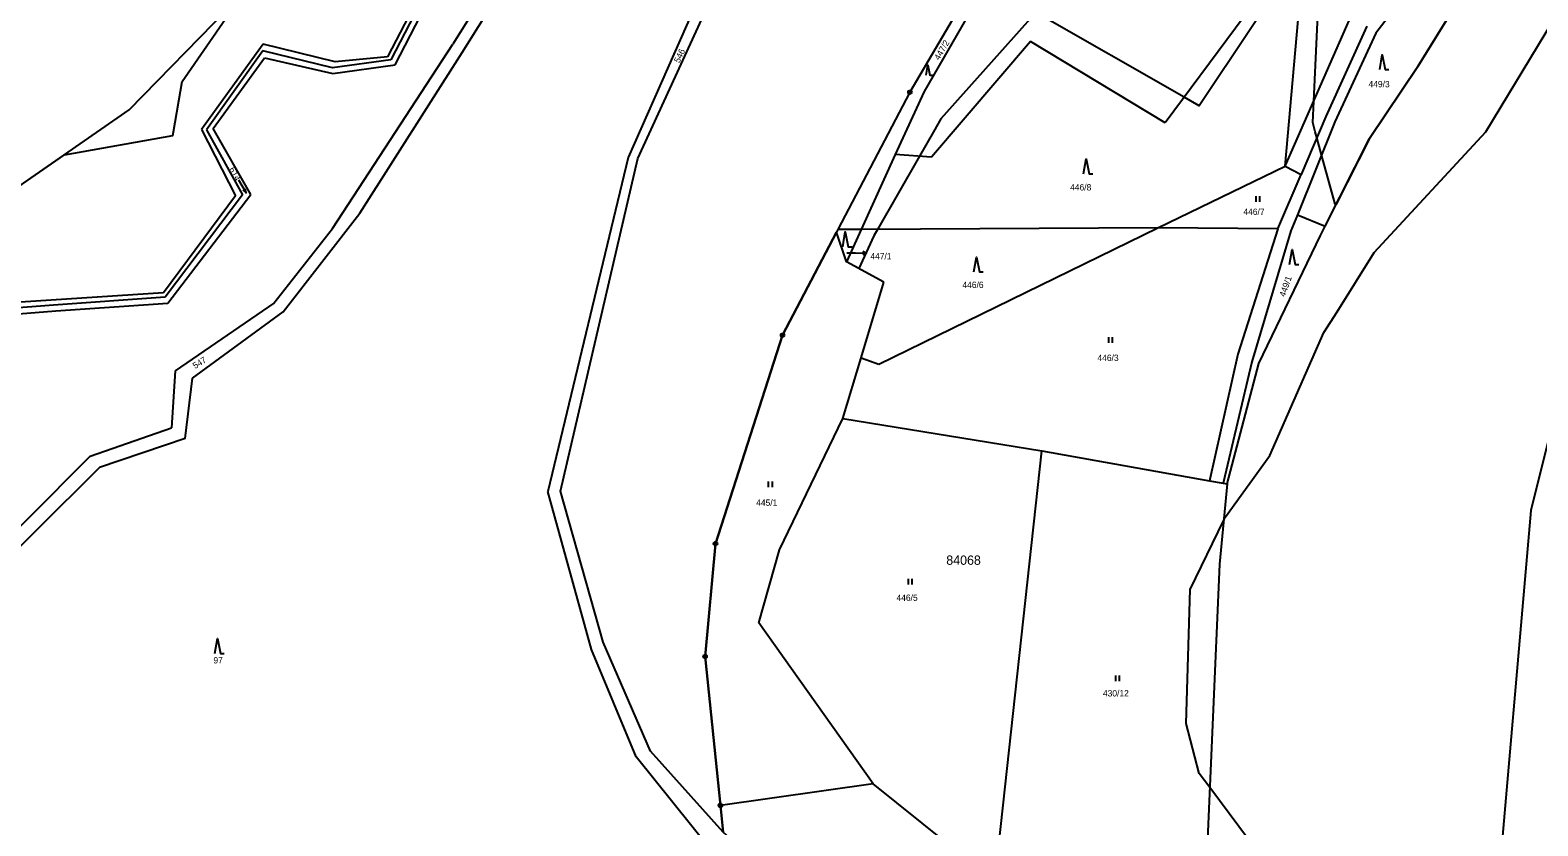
# Model space of a CAD drawing. Extents: x -547623 to -538651, y -1096714 to -1086522.
# Drawn here: x -544381.9 to -543976.5, y -1094186.5 to -1093972.7 of the extents above; entities that cross this region are included whole.
import ezdxf

# ---------------------------------------------------------------- set-up
doc = ezdxf.new("R2010")
doc.units = 0
for name, color, linetype in [('podzemní_provozovana', 7, 'Continuous'), ('Vrstva 1', 7, 'Continuous'), ('Vrstva 25', 7, 'Continuous'), ('Vrstva 41', 7, 'Continuous'), ('Vrstva 52', 7, 'Continuous'), ('Vrstva 53', 7, 'Continuous'), ('Vrstva 83', 7, 'Continuous'), ('Vrstva 86', 7, 'Continuous')]:
    doc.layers.add(name, color=color, linetype=linetype)

msp = doc.modelspace()

# ---------------------------------------------------------------- linework, layer by layer
at = {"layer": 'podzemní_provozovana'}
msp.add_line((-544159.95, -1094032.56), (-544156.95, -1094032.62), dxfattribs=at)
for points in [[(-544157.94, -1094032.1), (-544156.95, -1094032.62), (-544157.96, -1094033.1)], [(-544162.29, -1094032.52), (-544159.95, -1094032.56)]]:
    msp.add_lwpolyline(points, dxfattribs=at)
at = {"layer": 'Vrstva 1'}
for points in [[(-544231.42, -1093917.78), (-544268.23, -1093976.49)], [(-544265.71, -1093978.73), (-544229.5, -1093920.98)], [(-544102, -1093920.7), (-544141.53, -1093989.17)], [(-544038.86, -1093946.61), (-544076.64, -1093997.58)], [(-544044.44, -1094009.29), (-544038.86, -1093946.61)], [(-544196.54, -1093951.3), (-544221.1, -1094006.97)], [(-544218.52, -1094007.2), (-544194.16, -1093954.3)], [(-544009.71, -1093960.09), (-544020, -1093973.55)], [(-544355.24, -1093994.15), (-544328.67, -1093966.87)], [(-544008.7, -1093982.5), (-543998.69, -1093966.28)], [(-544280.03, -1093968.88), (-544285.81, -1093979.92)], [(-544283.7, -1093982.03), (-544276.92, -1093968.88)], [(-544044.44, -1094009.29), (-544026.22, -1093967.89)], [(-544022.47, -1093971.59), (-544033.52, -1093995.88)], [(-544020, -1093973.55), (-544031.03, -1093997.36)], [(-544319.25, -1093976.47), (-544335.83, -1093999.42)], [(-544299.85, -1093981.24), (-544319.25, -1093976.47)], [(-544300.62, -1094025.98), (-544268.23, -1093976.49)], [(-544293.25, -1094021.87), (-544265.71, -1093978.73)], [(-544112.85, -1093975.79), (-544139.51, -1094006.81)], [(-544076.64, -1093997.58), (-544112.85, -1093975.79)], [(-544332.64, -1093999.18), (-544318.88, -1093980.1)], [(-544318.88, -1093980.1), (-544300.51, -1093984.31)], [(-544300.51, -1093984.31), (-544283.7, -1093982.03)], [(-544285.81, -1093979.92), (-544299.85, -1093981.24)], [(-544021.73, -1094001.81), (-544008.7, -1093982.5)], [(-544141.53, -1093989.17), (-544149.24, -1094006.09)], [(-544410.07, -1094032.13), (-544355.24, -1093994.15)], [(-544335.83, -1093999.42), (-544326.66, -1094017.24)], [(-544322.54, -1094016.84), (-544332.64, -1093999.18)], [(-544031.03, -1093997.36), (-544041.14, -1094022.36)], [(-544033.52, -1093995.88), (-544040.1, -1094011.54)], [(-544033.7, -1094025.42), (-544021.73, -1094001.81)], [(-544221.1, -1094006.97), (-544242.67, -1094096.71)], [(-544239.27, -1094096.59), (-544218.52, -1094007.2)], [(-544149.24, -1094006.09), (-544158.44, -1094026.27)], [(-544139.51, -1094006.81), (-544149.24, -1094006.09)], [(-544078.66, -1094025.81), (-544044.44, -1094009.29)], [(-544046.35, -1094026.08), (-544040.1, -1094011.54)], [(-544044.44, -1094009.29), (-544040.1, -1094011.54)], [(-544326.66, -1094017.24), (-544346.05, -1094043.34)], [(-544344.82, -1094046.07), (-544322.54, -1094016.84)], [(-544313.87, -1094048.39), (-544293.25, -1094021.87)], [(-544041.14, -1094022.36), (-544042.86, -1094026.62)], [(-544041.14, -1094022.36), (-544033.7, -1094025.42)], [(-544316.39, -1094046.05), (-544300.62, -1094025.98)], [(-544162.39, -1094034.94), (-544165.03, -1094027)], [(-544158.44, -1094026.27), (-544164.67, -1094026.31)], [(-544158.44, -1094026.27), (-544162.39, -1094034.94)], [(-544078.66, -1094025.81), (-544158.44, -1094026.27)], [(-544153.64, -1094062.5), (-544078.66, -1094025.81)], [(-544046.35, -1094026.08), (-544078.66, -1094025.81)], [(-544046.35, -1094026.08), (-544057.12, -1094059.74)], [(-544042.86, -1094026.62), (-544053.35, -1094061.85)], [(-544051.48, -1094062.27), (-544034.93, -1094027.86)], [(-544034.93, -1094027.86), (-544033.7, -1094025.42)], [(-544152.29, -1094040.4), (-544162.39, -1094034.94)], [(-544346.05, -1094043.34), (-544402.42, -1094047)], [(-544158.46, -1094060.77), (-544152.29, -1094040.4)], [(-544402.9, -1094050.36), (-544374.99, -1094048.1)], [(-544374.99, -1094048.1), (-544344.82, -1094046.07)], [(-544316.39, -1094046.05), (-544342.89, -1094064.27)], [(-544338.23, -1094066.23), (-544313.87, -1094048.39)], [(-544057.12, -1094059.74), (-544064.76, -1094093.78)], [(-544342.89, -1094064.27), (-544343.83, -1094079.59)], [(-544163.4, -1094077.09), (-544158.46, -1094060.77)], [(-544158.46, -1094060.77), (-544153.64, -1094062.5)], [(-544053.35, -1094061.85), (-544061.05, -1094094.44)], [(-544060, -1094094.63), (-544051.48, -1094062.27)], [(-544340.19, -1094082.48), (-544338.23, -1094066.23)], [(-544365.78, -1094087.21), (-544343.83, -1094079.59)], [(-544180.36, -1094112.35), (-544163.4, -1094077.09)], [(-544163.4, -1094077.09), (-544109.88, -1094085.75)], [(-544340.19, -1094082.48), (-544363.19, -1094090.2)], [(-543973.55, -1094082.37), (-543978.37, -1094101.76)], [(-544416.41, -1094138.02), (-544365.78, -1094087.21)], [(-544122.46, -1094201.51), (-544109.88, -1094085.75)], [(-544109.88, -1094085.75), (-544064.76, -1094093.78)], [(-544363.19, -1094090.2), (-544414.72, -1094141.32)], [(-544230.9, -1094139.17), (-544242.67, -1094096.71)], [(-544227.81, -1094137.2), (-544239.27, -1094096.59)], [(-544064.76, -1094093.78), (-544061.05, -1094094.44)], [(-544060, -1094094.63), (-544062.06, -1094116.25)], [(-544061.05, -1094094.44), (-544060, -1094094.63)], [(-543978.37, -1094101.76), (-543987.94, -1094211.97)], [(-544185.92, -1094132.01), (-544180.36, -1094112.35)], [(-544062.06, -1094116.25), (-544065.57, -1094196.37)], [(-544155.2, -1094175.25), (-544185.92, -1094132.01)], [(-544215.09, -1094166.51), (-544227.81, -1094137.2)], [(-544218.93, -1094167.98), (-544230.9, -1094139.17)], [(-544199.18, -1094192.56), (-544218.93, -1094167.98)], [(-544195.57, -1094188.27), (-544215.09, -1094166.51)], [(-544155.2, -1094175.25), (-544196.28, -1094181.04)], [(-544122.46, -1094201.51), (-544155.2, -1094175.25)]]:
    msp.add_lwpolyline(points, dxfattribs=at)
at = {"layer": 'Vrstva 25'}
for p, q in [((-544052.2, -1094018.8), (-544052.2, -1094017.3)), ((-544051.2, -1094018.8), (-544051.2, -1094017.3)), ((-544091.84, -1094056.71), (-544091.84, -1094055.21)), ((-544090.84, -1094056.71), (-544090.84, -1094055.21)), ((-544183.31, -1094095.49), (-544183.31, -1094093.99)), ((-544182.31, -1094095.49), (-544182.31, -1094093.99)), ((-544145.73, -1094121.66), (-544145.73, -1094120.16)), ((-544144.73, -1094121.66), (-544144.73, -1094120.16)), ((-544089.96, -1094147.67), (-544089.96, -1094146.17)), ((-544088.96, -1094147.67), (-544088.96, -1094146.17))]:
    msp.add_line(p, q, dxfattribs=at)
for points in [[(-544019, -1093983.3), (-544018.3, -1093979.3), (-544017.5, -1093983.3), (-544016.5, -1093983.3)], [(-544140.93, -1093984.8), (-544140.46, -1093982.12), (-544139.92, -1093984.8), (-544139.25, -1093984.8)], [(-544098.64, -1094011.33), (-544097.94, -1094007.33), (-544097.14, -1094011.33), (-544096.14, -1094011.33)], [(-544325.85, -1094012.96), (-544323.79, -1094016.42), (-544324.02, -1094015.38)], [(-544323.79, -1094016.42), (-544324.59, -1094015.72)], [(-544163.39, -1094030.94), (-544162.69, -1094026.94), (-544161.89, -1094030.94), (-544160.89, -1094030.94)], [(-544043.21, -1094035.68), (-544042.51, -1094031.68), (-544041.71, -1094035.68), (-544040.71, -1094035.68)], [(-544128.09, -1094037.68), (-544127.39, -1094033.68), (-544126.59, -1094037.68), (-544125.59, -1094037.68)], [(-544332.2, -1094140.2), (-544331.5, -1094136.2), (-544330.7, -1094140.2), (-544329.7, -1094140.2)]]:
    msp.add_lwpolyline(points, dxfattribs=at)
at = {"layer": 'Vrstva 41'}
for p, q in [((-544197.59, -1094110.71), (-544200.39, -1094141.05)), ((-544197.59, -1094110.71), (-544200.39, -1094141.05)), ((-544200.39, -1094141.05), (-544196.28, -1094181.04)), ((-544200.39, -1094141.05), (-544196.28, -1094181.04))]:
    msp.add_line(p, q, dxfattribs=at)
for points in [[(-544129.74, -1093962.73), (-544145.32, -1093989.4)], [(-544129.74, -1093962.73), (-544145.32, -1093989.4)], [(-544278.65, -1093968.55), (-544284.88, -1093980.64)], [(-544278.65, -1093968.55), (-544284.88, -1093980.64)], [(-544319.28, -1093978.27), (-544334.5, -1093999.47)], [(-544319.28, -1093978.27), (-544334.5, -1093999.47)], [(-544300.57, -1093982.84), (-544319.28, -1093978.27)], [(-544300.57, -1093982.84), (-544319.28, -1093978.27)], [(-544284.88, -1093980.64), (-544300.57, -1093982.84)], [(-544284.88, -1093980.64), (-544300.57, -1093982.84)], [(-544145.32, -1093989.4), (-544164.67, -1094026.31)], [(-544145.32, -1093989.4), (-544164.67, -1094026.31)], [(-544334.5, -1093999.47), (-544324.82, -1094016.96)], [(-544334.5, -1093999.47), (-544324.82, -1094016.96)], [(-544324.82, -1094016.96), (-544345.58, -1094044.45)], [(-544324.82, -1094016.96), (-544345.58, -1094044.45)], [(-544165.03, -1094027), (-544179.55, -1094054.7)], [(-544165.03, -1094027), (-544179.55, -1094054.7)], [(-544164.67, -1094026.31), (-544165.03, -1094027)], [(-544164.67, -1094026.31), (-544165.03, -1094027)], [(-544375.6, -1094046.63), (-544402.66, -1094048.68)], [(-544375.6, -1094046.63), (-544402.66, -1094048.68)], [(-544345.58, -1094044.45), (-544375.6, -1094046.63)], [(-544345.58, -1094044.45), (-544375.6, -1094046.63)], [(-544179.55, -1094054.7), (-544197.59, -1094110.71)], [(-544179.55, -1094054.7), (-544197.59, -1094110.71)], [(-544196.28, -1094181.04), (-544195.57, -1094188.27)], [(-544196.28, -1094181.04), (-544195.57, -1094188.27)]]:
    msp.add_lwpolyline(points, dxfattribs=at)
at = {"layer": 'Vrstva 52'}
for points in [[(-543990.5, -1094000), (-543964.5, -1093957), (-543953, -1093932), (-543944, -1093922.5)], [(-543998.69, -1093966.28), (-544008.7, -1093982.5), (-544021.73, -1094001.81), (-544030.7, -1094019.5), (-544031, -1094019.5), (-544034.62, -1094006.23), (-544035.9, -1094001.54), (-544036.32, -1094000), (-544037, -1093997.5), (-544036.74, -1093991.78), (-544034.5, -1093943.5)], [(-544039.21, -1093950.57), (-544067.5, -1093993), (-544071.54, -1093990.7), (-544111.5, -1093968), (-544137, -1093996.5), (-544139, -1094000), (-544142.75, -1094006.57), (-544154, -1094026.24), (-544155, -1094028), (-544159.03, -1094036.76), (-544162.39, -1094034.94), (-544165.03, -1094027)], [(-544524.38, -1094185.31), (-544524.27, -1094178.58), (-544523.92, -1094156.47), (-544523.91, -1094156.01), (-544523.5, -1094130), (-544517.5, -1094094), (-544502.36, -1094078.43), (-544496.76, -1094074.85), (-544464.18, -1094062.37), (-544419.38, -1094039.61), (-544410.07, -1094032.13), (-544372.61, -1094006.18), (-544343.5, -1094001), (-544343.33, -1094000), (-544341, -1093986.5), (-544328.5, -1093968.5)], [(-544051.5, -1094294), (-544051.17, -1094292.05), (-544049.81, -1094283.86), (-544047.27, -1094268.6), (-544047.1, -1094267.58), (-544047, -1094267), (-544040.2, -1094227.68), (-544040, -1094226.5), (-544042.3, -1094213.54), (-544044, -1094204), (-544046.2, -1094201.05), (-544064.69, -1094176.27), (-544067.5, -1094172.5), (-544071, -1094159), (-544070, -1094123), (-544060.93, -1094104.38), (-544060.5, -1094103.5), (-544048.5, -1094087), (-544034, -1094054), (-544030.47, -1094048.38), (-544020.5, -1094032.5), (-543990.5, -1094000)], [(-544104.72, -1094280.9), (-544102.27, -1094276.75), (-544101.28, -1094274.62), (-544097.95, -1094269.87), (-544109.15, -1094259.81), (-544125.6, -1094246.12), (-544130.63, -1094240.95), (-544144.91, -1094226.19), (-544173.38, -1094208.33), (-544195.57, -1094188.27), (-544196.28, -1094181.04), (-544200.39, -1094141.05), (-544197.59, -1094110.71), (-544179.55, -1094054.7), (-544165.03, -1094027)]]:
    msp.add_lwpolyline(points, dxfattribs=at)
at = {"layer": 'Vrstva 83'}
for centre, radius in [((-544145.32, -1093989.4), 0.5), ((-544145.32, -1093989.4), 0.1), ((-544179.55, -1094054.7), 0.5), ((-544179.55, -1094054.7), 0.1), ((-544197.59, -1094110.71), 0.5), ((-544197.59, -1094110.71), 0.1), ((-544200.39, -1094141.05), 0.5), ((-544200.39, -1094141.05), 0.1), ((-544196.28, -1094181.04), 0.5), ((-544196.28, -1094181.04), 0.1)]:
    msp.add_circle(centre, radius, dxfattribs=at)

# ---------------------------------------------------------------- texts
at = {"layer": 'podzemní_provozovana'}
msp.add_text('447/1', height=1.7, dxfattribs=at).set_placement((-544155.95, -1094034.32))
at = {"layer": 'Vrstva 53'}
msp.add_text('84068', height=2.5, dxfattribs=at).set_placement((-544135.54, -1094116.39))
at = {"layer": 'Vrstva 86'}
for s, rotation, p in [('546', 64.7507, (-544207.31, -1093981.66)), ('447/2', 59.8075, (-544137.45, -1093980.93)), ('614', 298.4117, (-544328.46, -1094010.07)), ('449/1', 70.9241, (-544044.45, -1094044.51)), ('547', 31.8418, (-544337.51, -1094063.81))]:
    msp.add_text(s, height=1.7, rotation=rotation, dxfattribs=at).set_placement(p)
for s, height, p in [('449/3', 1.7, (-544022, -1093988.05)), ('446/8', 1.7, (-544102.24, -1094015.79)), ('446/7', 1.7, (-544055.64, -1094022.35)), ('447/1', 0.1, (-544162.46, -1094032.52)), ('446/6', 1.7, (-544131.2, -1094042)), ('446/3', 1.7, (-544094.88, -1094061.6)), ('445/1', 1.7, (-544186.66, -1094100.54)), ('446/5', 1.7, (-544148.92, -1094126.08)), ('97', 1.7, (-544332.6, -1094142.9)), ('430/12', 1.7, (-544093.42, -1094151.77))]:
    msp.add_text(s, height=height, dxfattribs=at).set_placement(p)

doc.saveas('drawing.dxf')
